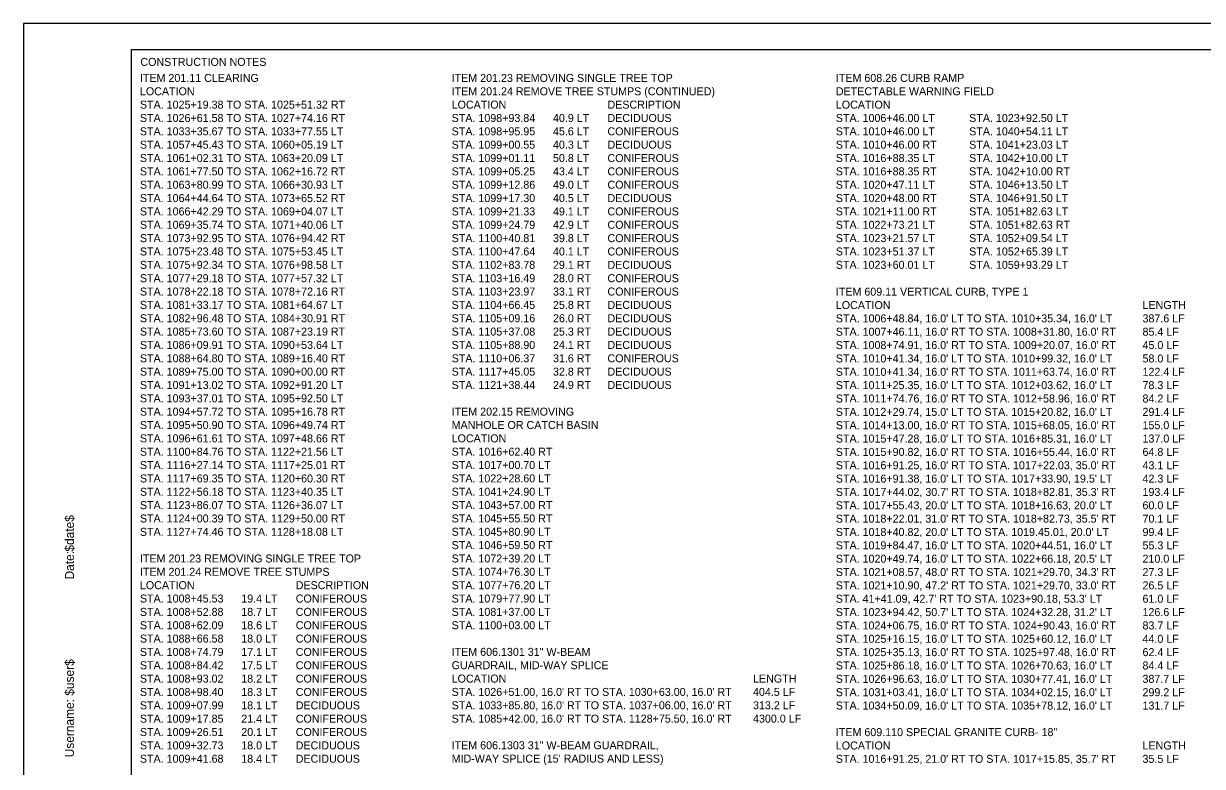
# Model space of a CAD drawing. Extents: x -831 to 3331, y -1004 to 250.
# Drawn here: x 102.6 to 544.6, y -693.8 to -415.1 of the extents above; entities that cross this region are included whole.
import ezdxf

# ---------------------------------------------------------------- set-up
doc = ezdxf.new("R2010")
doc.units = 0
for name, color, linetype in [('BORDER', 7, 'Continuous'), ('Default', 7, 'Continuous'), ('PLOT BOUNDARY', 7, 'Continuous')]:
    doc.layers.add(name, color=color, linetype=linetype)

msp = doc.modelspace()

# ---------------------------------------------------------------- linework, layer by layer
at = {"layer": 'BORDER'}
msp.add_lwpolyline([(143.03, -424.76), (943.03, -424.76), (943.03, -949.76), (143.03, -949.76)], close=True, dxfattribs=at)
at = {"layer": 'Default'}
msp.add_line((509.71, -424.76), (513.05, -424.76), dxfattribs=at)
at = {"layer": 'PLOT BOUNDARY'}
msp.add_lwpolyline([(102.57, -965.05), (952.57, -965.05), (952.57, -415.05), (102.57, -415.05)], close=True, dxfattribs=at)

# ---------------------------------------------------------------- texts
at = {"layer": 'BORDER'}
for s, p in [('$date$', (121.46, -613.23)), ('Date:', (121.46, -623.67)), ('$user$', (121.46, -667.3)), ('Username:', (121.46, -690.42))]:
    msp.add_text(s, height=3.348, rotation=90, dxfattribs=at).set_placement(p)
at = {"layer": 'Default'}
for s, p in [('CONSTRUCTION NOTES', (146.37, -430.94)), ('ITEM 201.11 CLEARING', (146.19, -436.96)), ('ITEM 201.23 REMOVING SINGLE TREE TOP', (263.08, -436.96)), ('ITEM 608.26 CURB RAMP ', (407.14, -436.96)), ('LOCATION', (146.19, -441.97)), ('ITEM 201.24 REMOVE TREE STUMPS (CONTINUED)', (263.08, -441.97)), ('DETECTABLE WARNING FIELD', (407.14, -441.97)), ('STA. 1025+19.38 TO STA. 1025+51.32 RT', (146.19, -446.98)), ('LOCATION', (263.08, -446.98)), ('DESCRIPTION', (321.51, -446.98)), ('LOCATION', (407.14, -446.98)), ('STA. 1026+61.58 TO STA. 1027+74.16 RT', (146.19, -451.99)), ('STA. 1098+93.84', (263.08, -451.99)), ('40.9 LT', (301.08, -451.99)), ('DECIDUOUS', (321.51, -451.99)), ('STA. 1006+46.00 LT', (407.14, -451.99)), ('STA. 1023+92.50 LT', (457.14, -451.99)), ('STA. 1033+35.67 TO STA. 1033+77.55 LT', (146.19, -457)), ('STA. 1098+95.95', (263.08, -457)), ('45.6 LT', (301.08, -457)), ('CONIFEROUS', (321.51, -457)), ('STA. 1010+46.00 LT', (407.14, -457)), ('STA. 1040+54.11 LT', (457.14, -457)), ('STA. 1057+45.43 TO STA. 1060+05.19 LT', (146.19, -462.01)), ('STA. 1099+00.55', (263.08, -462.01)), ('40.3 LT', (301.08, -462.01)), ('DECIDUOUS', (321.51, -462.01)), ('STA. 1010+46.00 RT', (407.14, -462.01)), ('STA. 1041+23.03 LT', (457.14, -462.01)), ('STA. 1061+02.31 TO STA. 1063+20.09 LT', (146.19, -467.02)), ('STA. 1099+01.11', (263.08, -467.02)), ('50.8 LT', (301.08, -467.02)), ('CONIFEROUS', (321.51, -467.02)), ('STA. 1016+88.35 LT', (407.14, -467.02)), ('STA. 1042+10.00 LT', (457.14, -467.02)), ('STA. 1061+77.50 TO STA. 1062+16.72 RT', (146.19, -472.03)), ('STA. 1099+05.25', (263.08, -472.03)), ('43.4 LT', (301.08, -472.03)), ('CONIFEROUS', (321.51, -472.03)), ('STA. 1016+88.35 RT', (407.14, -472.03)), ('STA. 1042+10.00 RT', (457.14, -472.03)), ('STA. 1063+80.99 TO STA. 1066+30.93 LT', (146.19, -477.04)), ('STA. 1099+12.86', (263.08, -477.04)), ('49.0 LT', (301.08, -477.04)), ('CONIFEROUS', (321.51, -477.04)), ('STA. 1020+47.11 LT', (407.14, -477.04)), ('STA. 1046+13.50 LT', (457.14, -477.04)), ('STA. 1064+44.64 TO STA. 1073+65.52 RT', (146.19, -482.05)), ('STA. 1099+17.30', (263.08, -482.05)), ('40.5 LT', (301.08, -482.05)), ('DECIDUOUS', (321.51, -482.05)), ('STA. 1020+48.00 RT', (407.14, -482.05)), ('STA. 1046+91.50 LT', (457.14, -482.05)), ('STA. 1066+42.29 TO STA. 1069+04.07 LT', (146.19, -487.06)), ('STA. 1099+21.33', (263.08, -487.06)), ('49.1 LT', (301.08, -487.06)), ('CONIFEROUS', (321.51, -487.06)), ('STA. 1021+11.00 RT', (407.14, -487.06)), ('STA. 1051+82.63 LT', (457.14, -487.06)), ('STA. 1069+35.74 TO STA. 1071+40.06 LT', (146.19, -492.07)), ('STA. 1099+24.79', (263.08, -492.07)), ('42.9 LT', (301.08, -492.07)), ('CONIFEROUS', (321.51, -492.07)), ('STA. 1022+73.21 LT', (407.14, -492.07)), ('STA. 1051+82.63 RT', (457.14, -492.07)), ('STA. 1073+92.95 TO STA. 1076+94.42 RT', (146.19, -497.08)), ('STA. 1100+40.81', (263.08, -497.08)), ('39.8 LT', (301.08, -497.08)), ('CONIFEROUS', (321.51, -497.08)), ('STA. 1023+21.57 LT', (407.14, -497.08)), ('STA. 1052+09.54 LT', (457.14, -497.08)), ('STA. 1075+23.48 TO STA. 1075+53.45 LT', (146.19, -502.09)), ('STA. 1100+47.64', (263.08, -502.09)), ('40.1 LT', (301.08, -502.09)), ('CONIFEROUS', (321.51, -502.09)), ('STA. 1023+51.37 LT', (407.14, -502.09)), ('STA. 1052+65.39 LT', (457.14, -502.09)), ('STA. 1075+92.34 TO STA. 1076+98.58 LT', (146.19, -507.1)), ('STA. 1102+83.78', (263.08, -507.1)), ('29.1 RT', (301.08, -507.1)), ('DECIDUOUS', (321.51, -507.1)), ('STA. 1023+60.01 LT', (407.14, -507.1)), ('STA. 1059+93.29 LT', (457.14, -507.1)), ('STA. 1077+29.18 TO STA. 1077+57.32 LT', (146.19, -512.11)), ('STA. 1103+16.49', (263.08, -512.11)), ('28.0 RT', (301.08, -512.11)), ('CONIFEROUS', (321.51, -512.11)), ('STA. 1078+22.18 TO STA. 1078+72.16 RT', (146.19, -517.12)), ('STA. 1103+23.97', (263.08, -517.12)), ('33.1 RT', (301.08, -517.12)), ('CONIFEROUS', (321.51, -517.12)), ('ITEM 609.11 VERTICAL CURB, TYPE 1', (407.14, -517.18)), ('STA. 1081+33.17 TO STA. 1081+64.67 LT', (146.19, -522.13)), ('STA. 1104+66.45', (263.08, -522.13)), ('25.8 RT', (301.08, -522.13)), ('DECIDUOUS', (321.51, -522.13)), ('LOCATION', (407.14, -522.19)), ('LENGTH', (522.14, -522.19)), ('STA. 1082+96.48 TO STA. 1084+30.91 RT', (146.19, -527.14)), ('STA. 1105+09.16', (263.08, -527.14)), ('26.0 RT', (301.08, -527.14)), ('DECIDUOUS', (321.51, -527.14)), ("STA. 1006+48.84, 16.0' LT TO STA. 1010+35.34, 16.0' LT", (407.14, -527.2)), ('387.6 LF', (522.14, -527.2)), ('STA. 1085+73.60 TO STA. 1087+23.19 RT', (146.19, -532.15)), ('STA. 1105+37.08', (263.08, -532.15)), ('25.3 RT', (301.08, -532.15)), ('DECIDUOUS', (321.51, -532.15)), ("STA. 1007+46.11, 16.0' RT TO STA. 1008+31.80, 16.0' RT", (407.14, -532.21)), ('85.4 LF', (522.14, -532.21)), ('STA. 1086+09.91 TO STA. 1090+53.64 LT', (146.19, -537.16)), ('STA. 1105+88.90', (263.08, -537.16)), ('24.1 RT', (301.08, -537.16)), ('DECIDUOUS', (321.51, -537.16)), ("STA. 1008+74.91, 16.0' RT TO STA. 1009+20.07, 16.0' RT", (407.14, -537.22)), ('45.0 LF', (522.14, -537.22)), ('STA. 1088+64.80 TO STA. 1089+16.40 RT', (146.19, -542.17)), ('STA. 1110+06.37', (263.08, -542.17)), ('31.6 RT', (301.08, -542.17)), ('CONIFEROUS', (321.51, -542.17)), ("STA. 1010+41.34, 16.0' LT TO STA. 1010+99.32, 16.0' LT", (407.14, -542.23)), ('58.0 LF', (522.14, -542.23)), ('STA. 1089+75.00 TO STA. 1090+00.00 RT', (146.19, -547.18)), ('STA. 1117+45.05', (263.08, -547.18)), ('32.8 RT', (301.08, -547.18)), ('DECIDUOUS', (321.51, -547.18)), ("STA. 1010+41.34, 16.0' RT TO STA. 1011+63.74, 16.0' RT", (407.14, -547.24)), ('122.4 LF', (522.14, -547.24)), ('STA. 1091+13.02 TO STA. 1092+91.20 LT', (146.19, -552.19)), ('STA. 1121+38.44', (263.08, -552.19)), ('24.9 RT', (301.08, -552.19)), ('DECIDUOUS', (321.51, -552.19)), ("STA. 1011+25.35, 16.0' LT TO STA. 1012+03.62, 16.0' LT ", (407.14, -552.25)), ('78.3 LF', (522.14, -552.25)), ('STA. 1093+37.01 TO STA. 1095+92.50 LT', (146.19, -557.2)), ("STA. 1011+74.76, 16.0' RT TO STA. 1012+58.96, 16.0' RT", (407.14, -557.26)), ('84.2 LF', (522.14, -557.26)), ('STA. 1094+57.72 TO STA. 1095+16.78 RT', (146.19, -562.21)), ('ITEM 202.15 REMOVING ', (263.08, -562.19)), ("STA. 1012+29.74, 15.0' LT TO STA. 1015+20.82, 16.0' LT", (407.14, -562.27)), ('291.4 LF', (522.14, -562.27)), ('STA. 1095+50.90 TO STA. 1096+49.74 RT', (146.19, -567.22)), ('MANHOLE OR CATCH BASIN', (263.08, -567.2)), ("STA. 1014+13.00, 16.0' RT TO STA. 1015+68.05, 16.0' RT", (407.14, -567.28)), ('155.0 LF', (522.14, -567.28)), ('STA. 1096+61.61 TO STA. 1097+48.66 RT', (146.19, -572.23)), ('LOCATION', (263.08, -572.21)), ("STA. 1015+47.28, 16.0' LT TO STA. 1016+85.31, 16.0' LT", (407.14, -572.29)), ('137.0 LF', (522.14, -572.29)), ('STA. 1100+84.76 TO STA. 1122+21.56 LT', (146.19, -577.24)), ('STA. 1016+62.40 RT', (263.08, -577.22)), ("STA. 1015+90.82, 16.0' RT TO STA. 1016+55.44, 16.0' RT", (407.14, -577.3)), ('64.8 LF', (522.14, -577.3)), ('STA. 1116+27.14 TO STA. 1117+25.01 RT', (146.19, -582.25)), ('STA. 1017+00.70 LT', (263.08, -582.23)), ("STA. 1016+91.25, 16.0' RT TO STA. 1017+22.03, 35.0' RT", (407.14, -582.31)), ('43.1 LF', (522.14, -582.31)), ('STA. 1117+69.35 TO STA. 1120+60.30 RT', (146.19, -587.26)), ('STA. 1022+28.60 LT', (263.08, -587.24)), ("STA. 1016+91.38, 16.0' LT TO STA. 1017+33.90, 19.5' LT", (407.14, -587.32)), ('42.3 LF', (522.14, -587.32)), ('STA. 1122+56.18 TO STA. 1123+40.35 LT', (146.19, -592.27)), ('STA. 1041+24.90 LT', (263.08, -592.25)), ("STA. 1017+44.02, 30.7' RT TO STA. 1018+82.81, 35.3' RT", (407.14, -592.33)), ('193.4 LF', (522.14, -592.33)), ('STA. 1123+86.07 TO STA. 1126+36.07 LT', (146.19, -597.28)), ('STA. 1043+57.00 RT', (263.08, -597.26)), ("STA. 1017+55.43, 20.0' LT TO STA. 1018+16.63, 20.0' LT", (407.14, -597.34)), ('60.0 LF', (522.14, -597.34)), ('STA. 1124+00.39 TO STA. 1129+50.00 RT', (146.19, -602.29)), ('STA. 1045+55.50 RT', (263.08, -602.27)), ("STA. 1018+22.01, 31.0' RT TO STA. 1018+82.73, 35.5' RT", (407.14, -602.35)), ('70.1 LF', (522.14, -602.35)), ('STA. 1127+74.46 TO STA. 1128+18.08 LT', (146.19, -607.3)), ('STA. 1045+80.90 LT', (263.08, -607.28)), ("STA. 1018+40.82, 20.0' LT TO STA. 1019.45.01, 20.0' LT", (407.14, -607.36)), ('99.4 LF', (522.14, -607.36)), ('STA. 1046+59.50 RT', (263.08, -612.29)), ("STA. 1019+84.47, 16.0' LT TO STA. 1020+44.51, 16.0' LT", (407.14, -612.37)), ('55.3 LF', (522.14, -612.37)), ('ITEM 201.23 REMOVING SINGLE TREE TOP', (146.19, -617.3)), ('STA. 1072+39.20 LT', (263.08, -617.3)), ("STA. 1020+49.74, 16.0' LT TO STA. 1022+66.18, 20.5' LT", (407.14, -617.38)), ('210.0 LF', (522.14, -617.38)), ('ITEM 201.24 REMOVE TREE STUMPS', (146.19, -622.31)), ('STA. 1074+76.30 LT', (263.08, -622.31)), ("STA. 1021+08.57, 48.0' RT TO STA. 1021+29.70, 34.3' RT", (407.14, -622.39)), ('27.3 LF', (522.14, -622.39)), ('LOCATION', (146.19, -627.32)), ('DESCRIPTION', (204.62, -627.32)), ('STA. 1077+76.20 LT', (263.08, -627.32)), ("STA. 1021+10.90, 47.2' RT TO STA. 1021+29.70, 33.0' RT", (407.14, -627.4)), ('26.5 LF', (522.14, -627.4)), ('STA. 1008+45.53', (146.19, -632.33)), ('19.4 LT', (184.19, -632.33)), ('CONIFEROUS', (204.62, -632.33)), ('STA. 1079+77.90 LT', (263.08, -632.33)), ("STA. 41+41.09, 42.7' RT TO STA. 1023+90.18, 53.3' LT", (407.14, -632.41)), ('61.0 LF', (522.14, -632.41)), ('STA. 1008+52.88', (146.19, -637.34)), ('18.7 LT', (184.19, -637.34)), ('CONIFEROUS', (204.62, -637.34)), ('STA. 1081+37.00 LT', (263.08, -637.34)), ("STA. 1023+94.42, 50.7' LT TO STA. 1024+32.28, 31.2' LT", (407.14, -637.42)), ('126.6 LF', (522.14, -637.42)), ('STA. 1008+62.09', (146.19, -642.35)), ('18.6 LT', (184.19, -642.35)), ('CONIFEROUS', (204.62, -642.35)), ('STA. 1100+03.00 LT', (263.08, -642.35)), ("STA. 1024+06.75, 16.0' RT TO STA. 1024+90.43, 16.0' RT", (407.14, -642.43)), ('83.7 LF', (522.14, -642.43)), ('STA. 1088+66.58', (146.19, -647.36)), ('18.0 LT', (184.19, -647.36)), ('CONIFEROUS', (204.62, -647.36)), ("STA. 1025+16.15, 16.0' LT TO STA. 1025+60.12, 16.0' LT", (407.14, -647.44)), ('44.0 LF', (522.14, -647.44)), ('STA. 1008+74.79', (146.19, -652.37)), ('17.1 LT', (184.19, -652.37)), ('CONIFEROUS', (204.62, -652.37)), ('ITEM 606.1301 31" W-BEAM ', (263.08, -652.35)), ("STA. 1025+35.13, 16.0' RT TO STA. 1025+97.48, 16.0' RT", (407.14, -652.45)), ('62.4 LF', (522.14, -652.45)), ('STA. 1008+84.42', (146.19, -657.38)), ('17.5 LT', (184.19, -657.38)), ('CONIFEROUS', (204.62, -657.38)), ('GUARDRAIL, MID-WAY SPLICE', (263.08, -657.36)), ("STA. 1025+86.18, 16.0' LT TO STA. 1026+70.63, 16.0' LT", (407.14, -657.46)), ('84.4 LF', (522.14, -657.46)), ('STA. 1008+93.02', (146.19, -662.39)), ('18.2 LT', (184.19, -662.39)), ('CONIFEROUS', (204.62, -662.39)), ('LOCATION', (263.08, -662.37)), ('LENGTH', (376.08, -662.37)), ("STA. 1026+96.63, 16.0' LT TO STA. 1030+77.41, 16.0' LT", (407.14, -662.47)), ('387.7 LF', (522.14, -662.47)), ('STA. 1008+98.40', (146.19, -667.4)), ('18.3 LT', (184.19, -667.4)), ('CONIFEROUS', (204.62, -667.4)), ("STA. 1026+51.00, 16.0' RT TO STA. 1030+63.00, 16.0' RT", (263.08, -667.38)), ('404.5 LF', (376.08, -667.38)), ("STA. 1031+03.41, 16.0' LT TO STA. 1034+02.15, 16.0' LT", (407.14, -667.48)), ('299.2 LF', (522.14, -667.48)), ('STA. 1009+07.99', (146.19, -672.41)), ('18.1 LT', (184.19, -672.41)), ('DECIDUOUS', (204.62, -672.41)), ("STA. 1033+85.80, 16.0' RT TO STA. 1037+06.00, 16.0' RT", (263.08, -672.39)), ('313.2 LF', (376.08, -672.39)), ("STA. 1034+50.09, 16.0' LT TO STA. 1035+78.12, 16.0' LT", (407.14, -672.49)), ('131.7 LF', (522.14, -672.49)), ('STA. 1009+17.85', (146.19, -677.42)), ('21.4 LT', (184.19, -677.42)), ('CONIFEROUS', (204.62, -677.42)), ("STA. 1085+42.00, 16.0' RT TO STA. 1128+75.50, 16.0' RT", (263.08, -677.4)), ('4300.0 LF', (376.08, -677.4)), ('STA. 1009+26.51', (146.19, -682.43)), ('20.1 LT', (184.19, -682.43)), ('CONIFEROUS', (204.62, -682.43)), ('ITEM 609.110 SPECIAL GRANITE CURB- 18"', (407.14, -682.47)), ('STA. 1009+32.73', (146.19, -687.44)), ('18.0 LT', (184.19, -687.44)), ('DECIDUOUS', (204.62, -687.44)), ('ITEM 606.1303 31" W-BEAM GUARDRAIL, ', (263.08, -687.4)), ('LOCATION', (407.14, -687.48)), ('LENGTH', (522.14, -687.48)), ('STA. 1009+41.68', (146.19, -692.45)), ('18.4 LT', (184.19, -692.45)), ('DECIDUOUS', (204.62, -692.45)), ("MID-WAY SPLICE (15' RADIUS AND LESS)", (263.08, -692.41)), ("STA. 1016+91.25, 21.0' RT TO STA. 1017+15.85, 35.7' RT", (407.14, -692.49)), ('35.5 LF', (522.14, -692.49))]:
    msp.add_text(s, height=3, dxfattribs=at).set_placement(p)

doc.saveas('drawing.dxf')
